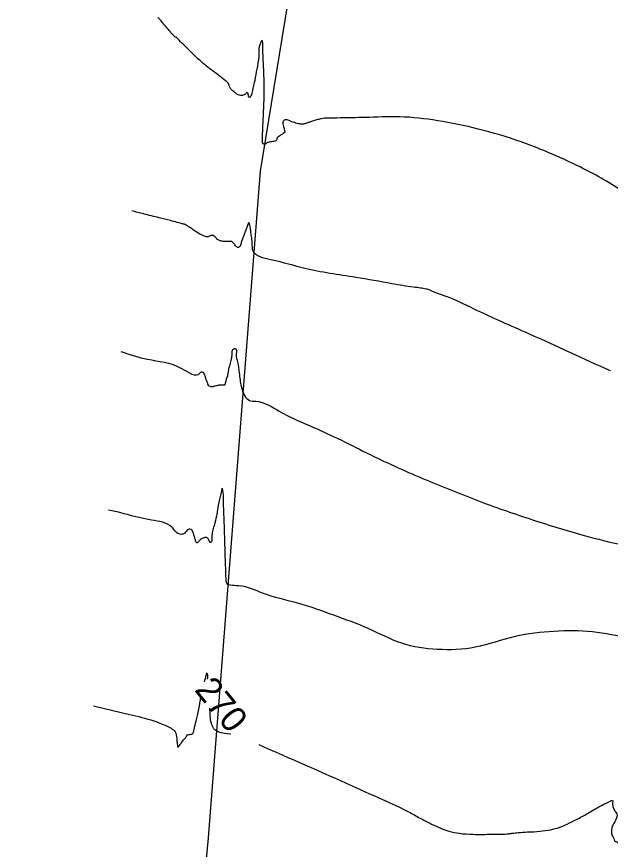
# Model space of a CAD drawing. Extents: x -478464 to -472469, y -1120963 to -1113785.
# Drawn here: x -477865.4 to -477772.6, y -1116848.4 to -1116718.3 of the extents above; entities that cross this region are included whole.
import ezdxf

# ---------------------------------------------------------------- set-up
doc = ezdxf.new("R2010")
doc.units = 0
for name, color, linetype in [('ObPÚ', 7, 'Continuous'), ('Vrstevnice_hlavni', 7, 'Continuous'), ('Vrstevnice_popis', 7, 'Continuous'), ('Vrstevnice_vedlejsi', 7, 'Continuous')]:
    doc.layers.add(name, color=color, linetype=linetype)

msp = doc.modelspace()

# ---------------------------------------------------------------- linework, layer by layer
at = {"layer": 'ObPÚ'}
for points in [[(-477835.42, -1116846.57), (-477827.27, -1116742.43), (-477820.03, -1116698.07), (-477819.21, -1116642.72), (-477821.57, -1116632.3), (-477837.97, -1116504.33), (-477857.08, -1116470.65), (-477873.54, -1116443.03), (-477876.37, -1116437.54), (-477908.62, -1116376.53), (-477932.52, -1116347.32), (-477968.13, -1116341.56), (-477983.23, -1116329.55), (-478000.09, -1116315.61), (-477992.63, -1116266.4), (-477967.7, -1116217.95), (-477949.03, -1116186.01)], [(-478036.665, -1117435.774), (-478026.64, -1117400.81), (-478007.71, -1117316.06), (-478010.688, -1117315.457), (-478014.916, -1117299.841), (-478003.02, -1117297.83), (-477955.02, -1117226.727), (-477932.94, -1117194.02), (-477930.86, -1117190.98), (-477927.765, -1117186.164), (-477902.42, -1117146.73), (-477898.94, -1117138.46), (-477889.78, -1117115.18), (-477874.35, -1117091.12), (-477871.53, -1117086.61), (-477868.88, -1117081.98), (-477862.66, -1117057.28), (-477855.79, -1117029.92), (-477851.66, -1117013.57), (-477838.11, -1116918.83), (-477838.17, -1116915.03), (-477838.53, -1116880.06), (-477835.42, -1116846.57)]]:
    msp.add_lwpolyline(points, dxfattribs=at)
at = {"layer": 'Vrstevnice_hlavni'}
for points in [[(-477827.558, -1116831.998), (-477812.966, -1116838.425), (-477807.513, -1116840.896), (-477803.903, -1116842.624), (-477802.138, -1116843.608), (-477800.542, -1116844.423), (-477799.117, -1116845.066), (-477797.862, -1116845.539), (-477796.181, -1116845.853), (-477794.075, -1116846.009), (-477791.543, -1116846.005), (-477789.687, -1116845.976), (-477788.506, -1116845.921), (-477788.002, -1116845.842), (-477787.021, -1116845.75), (-477785.564, -1116845.646), (-477783.63, -1116845.531), (-477781.95, -1116845.286), (-477780.526, -1116844.912), (-477779.357, -1116844.41), (-477777.912, -1116843.69), (-477776.193, -1116842.753), (-477774.198, -1116841.599), (-477772.882, -1116840.937), (-477772.244, -1116840.766), (-477772.285, -1116841.087), (-477772.28, -1116841.39), (-477772.229, -1116841.674), (-477772.131, -1116841.94), (-477771.997, -1116842.221), (-477771.826, -1116842.516), (-477771.618, -1116842.826), (-477771.619, -1116843.272), (-477771.83, -1116843.853), (-477772.25, -1116844.57), (-477772.45, -1116845.244), (-477772.429, -1116845.873), (-477772.188, -1116846.459), (-477772.015, -1116846.858), (-477771.91, -1116847.072), (-477771.873, -1116847.1), (-477771.835, -1116847.123), (-477771.796, -1116847.14), (-477771.757, -1116847.153), (-477771.45, -1116847.268), (-477770.875, -1116847.485), (-477770.032, -1116847.803), (-477769.437, -1116848.001), (-477769.09, -1116848.077), (-477768.992, -1116848.033), (-477768.646, -1116847.531), (-477768.052, -1116846.573), (-477767.209, -1116845.157), (-477766.581, -1116844.16), (-477766.166, -1116843.581), (-477765.966, -1116843.419), (-477765.542, -1116843.116), (-477764.896, -1116842.671), (-477764.027, -1116842.083), (-477763.323, -1116841.576), (-477762.784, -1116841.151), (-477762.409, -1116840.807), (-477762.15, -1116840.383), (-477762.008, -1116839.879), (-477761.983, -1116839.295), (-477761.788, -1116838.762), (-477761.423, -1116838.28), (-477760.89, -1116837.85), (-477760.615, -1116837.412), (-477760.599, -1116836.967), (-477760.843, -1116836.516), (-477761.054, -1116836.049), (-477761.233, -1116835.567), (-477761.381, -1116835.071), (-477761.595, -1116834.423), (-477761.876, -1116833.624), (-477762.222, -1116832.673), (-477762.366, -1116831.787), (-477762.306, -1116830.964), (-477762.044, -1116830.207), (-477761.6, -1116829.386), (-477760.975, -1116828.504), (-477760.17, -1116827.56), (-477759.14, -1116826.477), (-477757.886, -1116825.256), (-477756.407, -1116823.897), (-477754.744, -1116822.36), (-477752.896, -1116820.644), (-477750.863, -1116818.75), (-477748.889, -1116817.007), (-477746.973, -1116815.415), (-477745.115, -1116813.974), (-477743.594, -1116812.741), (-477742.41, -1116811.718), (-477741.564, -1116810.902), (-477739.116, -1116809.127), (-477735.067, -1116806.392)], [(-477835.531, -1116821.778), (-477835.601, -1116820.887), (-477835.67, -1116820.785), (-477835.774, -1116821.027), (-477836.052, -1116822.196)], [(-477853.382, -1116825.923), (-477848.151, -1116827.193), (-477844.404, -1116828.131), (-477841.854, -1116829.13), (-477840.501, -1116830.19), (-477840.345, -1116831.31), (-477840.241, -1116832.058), (-477840.189, -1116832.434), (-477840.188, -1116832.439), (-477840.187, -1116832.442), (-477840.186, -1116832.443), (-477840.185, -1116832.442), (-477840.01, -1116832.214), (-477839.662, -1116831.758), (-477839.141, -1116831.075), (-477838.766, -1116830.625), (-477838.538, -1116830.409), (-477838.457, -1116830.426), (-477838.325, -1116830.414), (-477838.144, -1116830.374), (-477837.912, -1116830.305), (-477837.636, -1116829.626), (-477837.316, -1116828.336), (-477836.589, -1116824.535)], [(-477831.923, -1116830.351), (-477833.864, -1116830.014), (-477834.547, -1116829.509), (-477834.945, -1116828.667), (-477835.166, -1116826.308)]]:
    msp.add_spline(points, degree=3, dxfattribs=at)
at = {"layer": 'Vrstevnice_vedlejsi'}
for points in [[(-477671.877, -1116765.485), (-477670.107, -1116763.213), (-477668.344, -1116760.437), (-477666.589, -1116757.155), (-477664.842, -1116753.369), (-477663.127, -1116749.565), (-477661.444, -1116745.744), (-477659.794, -1116741.906), (-477658.605, -1116739.257), (-477657.877, -1116737.797), (-477657.61, -1116737.527), (-477657.203, -1116736.404), (-477656.656, -1116734.428), (-477655.969, -1116731.6), (-477655.201, -1116729.073), (-477654.351, -1116726.846), (-477653.419, -1116724.919), (-477652.814, -1116723.593), (-477652.535, -1116722.868), (-477652.582, -1116722.743), (-477652.498, -1116722.443), (-477652.282, -1116721.967), (-477651.935, -1116721.316), (-477651.874, -1116718.859), (-477652.098, -1116714.597), (-477652.607, -1116708.529), (-477653.037, -1116704.344), (-477653.388, -1116702.042), (-477653.659, -1116701.622), (-477654.184, -1116701.48), (-477654.964, -1116701.615), (-477655.998, -1116702.028), (-477656.737, -1116702.308), (-477657.18, -1116702.456), (-477657.329, -1116702.471), (-477657.444, -1116702.497), (-477657.526, -1116702.532), (-477657.574, -1116702.577), (-477657.634, -1116702.632), (-477657.703, -1116702.696), (-477657.784, -1116702.771), (-477657.918, -1116702.895), (-477658.107, -1116703.069), (-477658.35, -1116703.291), (-477659.856, -1116704.866), (-477662.624, -1116707.794), (-477666.655, -1116712.075), (-477669.681, -1116715.287), (-477671.701, -1116717.43), (-477672.715, -1116718.505), (-477674.927, -1116720.563), (-477678.337, -1116723.605), (-477682.945, -1116727.629), (-477686.809, -1116731.391), (-477689.929, -1116734.889), (-477692.305, -1116738.124), (-477694.334, -1116740.842), (-477696.017, -1116743.043), (-477697.355, -1116744.727), (-477699.317, -1116746.572), (-477701.903, -1116748.578), (-477705.114, -1116750.745), (-477707.291, -1116752.202), (-477708.435, -1116752.95), (-477708.545, -1116752.987), (-477708.8, -1116753.08), (-477709.2, -1116753.23), (-477709.744, -1116753.436), (-477711.046, -1116753.937), (-477713.108, -1116754.733), (-477715.928, -1116755.824), (-477718.001, -1116756.646), (-477719.326, -1116757.2), (-477719.905, -1116757.484), (-477722.63, -1116757.561), (-477727.503, -1116757.43), (-477734.522, -1116757.092), (-477741.253, -1116756.366), (-477747.694, -1116755.252), (-477753.847, -1116753.751), (-477760.155, -1116751.374), (-477766.619, -1116748.119), (-477773.238, -1116743.988), (-477779.889, -1116740.564), (-477786.572, -1116737.847), (-477793.286, -1116735.837), (-477799.596, -1116734.532), (-477805.503, -1116733.931), (-477811.006, -1116734.034), (-477814.803, -1116734.106), (-477816.895, -1116734.146), (-477817.281, -1116734.155), (-477817.76, -1116734.228), (-477818.332, -1116734.366), (-477818.998, -1116734.568), (-477819.589, -1116734.753), (-477820.106, -1116734.921)], [(-477820.106, -1116734.921), (-477820.549, -1116735.072), (-477821.173, -1116735.045), (-477821.981, -1116734.84), (-477822.97, -1116734.458), (-477823.572, -1116734.456), (-477823.786, -1116734.834), (-477823.612, -1116735.593), (-477823.499, -1116736.097), (-477823.448, -1116736.347), (-477823.458, -1116736.343), (-477823.596, -1116736.432), (-477823.861, -1116736.614), (-477824.255, -1116736.89), (-477824.519, -1116737.076), (-477824.654, -1116737.174), (-477824.661, -1116737.183), (-477824.666, -1116737.196), (-477824.67, -1116737.212), (-477824.674, -1116737.232), (-477824.699, -1116737.302), (-477824.746, -1116737.422), (-477824.816, -1116737.592), (-477825.01, -1116737.72), (-477825.329, -1116737.806), (-477825.773, -1116737.851), (-477826.098, -1116737.916), (-477826.305, -1116738.001), (-477826.394, -1116738.108), (-477826.502, -1116738.173), (-477826.628, -1116738.195), (-477826.773, -1116738.176), (-477826.873, -1116738.127), (-477826.927, -1116738.05), (-477826.936, -1116737.944), (-477826.944, -1116737.771), (-477826.951, -1116737.529), (-477826.956, -1116737.221), (-477826.924, -1116736.205), (-477826.853, -1116734.483), (-477826.743, -1116732.053), (-477826.713, -1116729.396), (-477826.761, -1116726.511), (-477826.889, -1116723.398), (-477827.063, -1116722.032), (-477827.286, -1116722.412), (-477827.555, -1116724.54), (-477827.852, -1116726.484), (-477828.176, -1116728.244), (-477828.526, -1116729.82), (-477828.81, -1116730.714), (-477829.027, -1116730.925), (-477829.177, -1116730.453), (-477829.314, -1116730.194), (-477829.437, -1116730.148), (-477829.546, -1116730.314), (-477829.719, -1116730.447), (-477829.955, -1116730.548), (-477830.255, -1116730.615), (-477830.585, -1116730.56), (-477830.947, -1116730.383), (-477831.339, -1116730.083), (-477831.641, -1116729.836), (-477831.853, -1116729.642), (-477831.973, -1116729.5), (-477832.076, -1116729.318), (-477832.16, -1116729.096), (-477832.227, -1116728.834), (-477832.751, -1116728.303), (-477833.732, -1116727.501), (-477835.17, -1116726.431), (-477836.544, -1116725.297), (-477837.854, -1116724.101), (-477839.101, -1116722.843), (-477839.98, -1116721.977), (-477840.493, -1116721.503), (-477840.638, -1116721.421), (-477840.861, -1116721.218), (-477841.162, -1116720.893), (-477841.541, -1116720.446), (-477842.984, -1116718.745), (-477843.255, -1116718.425)], [(-477772.631, -1116773.632), (-477785.255, -1116767.876), (-477793.907, -1116763.957), (-477798.586, -1116761.876), (-477799.293, -1116761.634), (-477799.897, -1116761.407), (-477800.396, -1116761.198), (-477800.793, -1116761.005), (-477801.42, -1116760.833), (-477802.278, -1116760.681), (-477803.366, -1116760.549), (-477806.739, -1116759.994), (-477812.396, -1116759.015), (-477820.338, -1116757.613), (-477825.679, -1116756.25), (-477828.422, -1116754.925), (-477828.564, -1116753.639), (-477828.685, -1116752.598), (-477828.783, -1116751.801), (-477828.86, -1116751.249), (-477828.934, -1116750.846), (-477829.006, -1116750.593), (-477829.076, -1116750.49), (-477829.138, -1116750.479), (-477829.193, -1116750.559), (-477829.241, -1116750.73), (-477829.363, -1116751.08), (-477829.56, -1116751.609), (-477829.832, -1116752.317), (-477830.072, -1116752.971), (-477830.282, -1116753.571), (-477830.461, -1116754.117), (-477830.698, -1116754.345), (-477830.991, -1116754.255), (-477831.341, -1116753.847), (-477831.583, -1116753.573), (-477831.717, -1116753.433), (-477831.742, -1116753.428), (-477831.766, -1116753.424), (-477831.789, -1116753.421), (-477831.81, -1116753.419), (-477832.041, -1116753.412), (-477832.482, -1116753.402), (-477833.133, -1116753.388), (-477833.663, -1116753.259), (-477834.073, -1116753.015), (-477834.362, -1116752.657), (-477834.683, -1116752.48), (-477835.036, -1116752.486), (-477835.422, -1116752.673), (-477835.997, -1116752.59), (-477836.761, -1116752.236), (-477837.716, -1116751.611), (-477838.393, -1116751.168), (-477838.793, -1116750.906), (-477838.916, -1116750.824), (-477839.04, -1116750.762), (-477839.166, -1116750.719), (-477839.292, -1116750.696), (-477839.517, -1116750.638), (-477839.841, -1116750.546), (-477840.264, -1116750.42), (-477841.351, -1116750.138), (-477843.102, -1116749.699), (-477845.516, -1116749.104), (-477847.381, -1116748.62)], [(-477849.086, -1116770.578), (-477844.91, -1116771.794), (-477839.505, -1116773.285), (-477836.696, -1116773.945), (-477836.484, -1116773.773), (-477836.278, -1116773.837), (-477836.08, -1116774.139), (-477835.889, -1116774.678), (-477835.721, -1116775.144), (-477835.577, -1116775.535), (-477835.456, -1116775.853), (-477835.203, -1116776.026), (-477834.82, -1116776.052), (-477834.306, -1116775.932), (-477833.951, -1116775.848), (-477833.756, -1116775.801), (-477833.722, -1116775.79), (-477833.623, -1116775.784), (-477833.459, -1116775.785), (-477833.232, -1116775.792), (-477833.055, -1116775.8), (-477832.931, -1116775.808), (-477832.858, -1116775.819), (-477832.787, -1116775.713), (-477832.717, -1116775.493), (-477832.65, -1116775.157), (-477832.591, -1116774.904), (-477832.54, -1116774.733), (-477832.498, -1116774.645), (-477832.347, -1116774.002), (-477832.088, -1116772.803), (-477831.72, -1116771.049), (-477831.427, -1116770.161), (-477831.21, -1116770.14), (-477831.067, -1116770.985), (-477830.866, -1116772.248), (-477830.605, -1116773.928), (-477830.284, -1116776.025), (-477829.746, -1116777.462), (-477828.99, -1116778.24), (-477828.015, -1116778.357), (-477824.361, -1116779.897), (-477818.027, -1116782.858), (-477809.014, -1116787.242), (-477800.303, -1116791.092), (-477791.895, -1116794.41), (-477783.789, -1116797.195), (-477776.707, -1116799.325), (-477770.649, -1116800.8), (-477765.614, -1116801.62), (-477762.206, -1116802.153), (-477760.426, -1116802.399), (-477760.273, -1116802.358), (-477759.926, -1116802.252), (-477759.387, -1116802.081), (-477758.655, -1116801.844), (-477756.76, -1116801.017), (-477753.701, -1116799.599), (-477749.48, -1116797.59), (-477746.067, -1116796.125), (-477743.463, -1116795.202), (-477741.667, -1116794.823), (-477740.402, -1116794.54), (-477739.667, -1116794.353), (-477739.462, -1116794.263), (-477737.401, -1116792.609), (-477733.484, -1116789.393), (-477727.711, -1116784.615), (-477723.289, -1116781.046), (-477720.218, -1116778.688), (-477718.498, -1116777.54), (-477716.122, -1116775.985), (-477713.092, -1116774.022), (-477709.407, -1116771.653), (-477705.96, -1116769.437), (-477702.749, -1116767.376), (-477699.776, -1116765.468), (-477697.579, -1116764.052), (-477696.159, -1116763.126)], [(-477704.057, -1116781.604), (-477703.642, -1116780.675), (-477703.306, -1116779.984), (-477703.05, -1116779.532), (-477702.873, -1116779.318), (-477702.618, -1116778.781), (-477702.286, -1116777.921), (-477701.877, -1116776.739), (-477701.893, -1116776.136), (-477702.334, -1116776.113), (-477703.202, -1116776.669), (-477703.961, -1116777.157), (-477704.613, -1116777.575), (-477705.156, -1116777.925), (-477706.931, -1116779.1), (-477709.937, -1116781.102), (-477714.174, -1116783.93), (-477717.848, -1116786.517), (-477720.957, -1116788.865), (-477723.503, -1116790.972), (-477726.774, -1116793.406), (-477730.769, -1116796.167), (-477735.49, -1116799.254), (-477739.404, -1116802.05), (-477742.51, -1116804.556), (-477744.809, -1116806.771), (-477746.791, -1116808.596), (-477748.457, -1116810.032), (-477749.805, -1116811.078), (-477750.841, -1116811.807), (-477751.565, -1116812.218), (-477751.976, -1116812.312), (-477752.475, -1116812.491), (-477753.063, -1116812.755), (-477753.739, -1116813.104), (-477754.889, -1116813.563), (-477756.513, -1116814.131), (-477758.611, -1116814.809), (-477760.347, -1116815.351), (-477761.721, -1116815.756), (-477762.733, -1116816.025), (-477765.356, -1116815.887), (-477769.588, -1116815.342), (-477775.431, -1116814.391), (-477781.407, -1116814.313), (-477787.518, -1116815.11), (-477793.762, -1116816.78), (-477799.664, -1116817.13), (-477805.221, -1116816.159), (-477810.436, -1116813.868), (-477815.797, -1116811.8), (-477821.305, -1116809.954), (-477826.961, -1116808.33), (-477830.735, -1116807.198), (-477832.628, -1116806.557), (-477832.639, -1116806.408), (-477832.658, -1116805.946), (-477832.686, -1116805.17), (-477832.721, -1116804.081), (-477832.781, -1116802.195), (-477832.865, -1116799.512), (-477832.974, -1116796.032), (-477833.063, -1116793.635), (-477833.134, -1116792.323), (-477833.187, -1116792.094), (-477833.236, -1116791.971), (-477833.282, -1116791.954), (-477833.324, -1116792.042), (-477833.537, -1116793.021), (-477833.92, -1116794.89), (-477834.474, -1116797.65), (-477834.864, -1116799.487), (-477835.089, -1116800.401), (-477835.15, -1116800.393), (-477835.21, -1116800.335), (-477835.269, -1116800.227), (-477835.327, -1116800.069), (-477835.401, -1116799.925), (-477835.491, -1116799.795), (-477835.598, -1116799.679), (-477835.761, -1116799.628), (-477835.98, -1116799.642), (-477836.257, -1116799.722), (-477836.487, -1116799.835), (-477836.673, -1116799.983), (-477836.813, -1116800.165), (-477836.951, -1116800.307), (-477837.087, -1116800.409), (-477837.221, -1116800.471), (-477837.329, -1116800.404), (-477837.41, -1116800.207), (-477837.464, -1116799.88), (-477837.578, -1116799.488), (-477837.75, -1116799.032), (-477837.981, -1116798.511), (-477838.308, -1116798.341), (-477838.731, -1116798.52)], [(-477838.731, -1116798.52), (-477839.251, -1116799.05), (-477839.825, -1116799.14), (-477840.456, -1116798.791), (-477841.141, -1116798.003), (-477844.311, -1116796.938), (-477849.964, -1116795.596), (-477851.011, -1116795.385)]]:
    msp.add_spline(points, degree=3, dxfattribs=at)

# ---------------------------------------------------------------- texts
at = {"layer": 'Vrstevnice_popis'}
msp.add_text(' 270 ', height=4, rotation=308.73901, dxfattribs=at).set_placement((-477838.628, -1116822.312))

doc.saveas('drawing.dxf')
